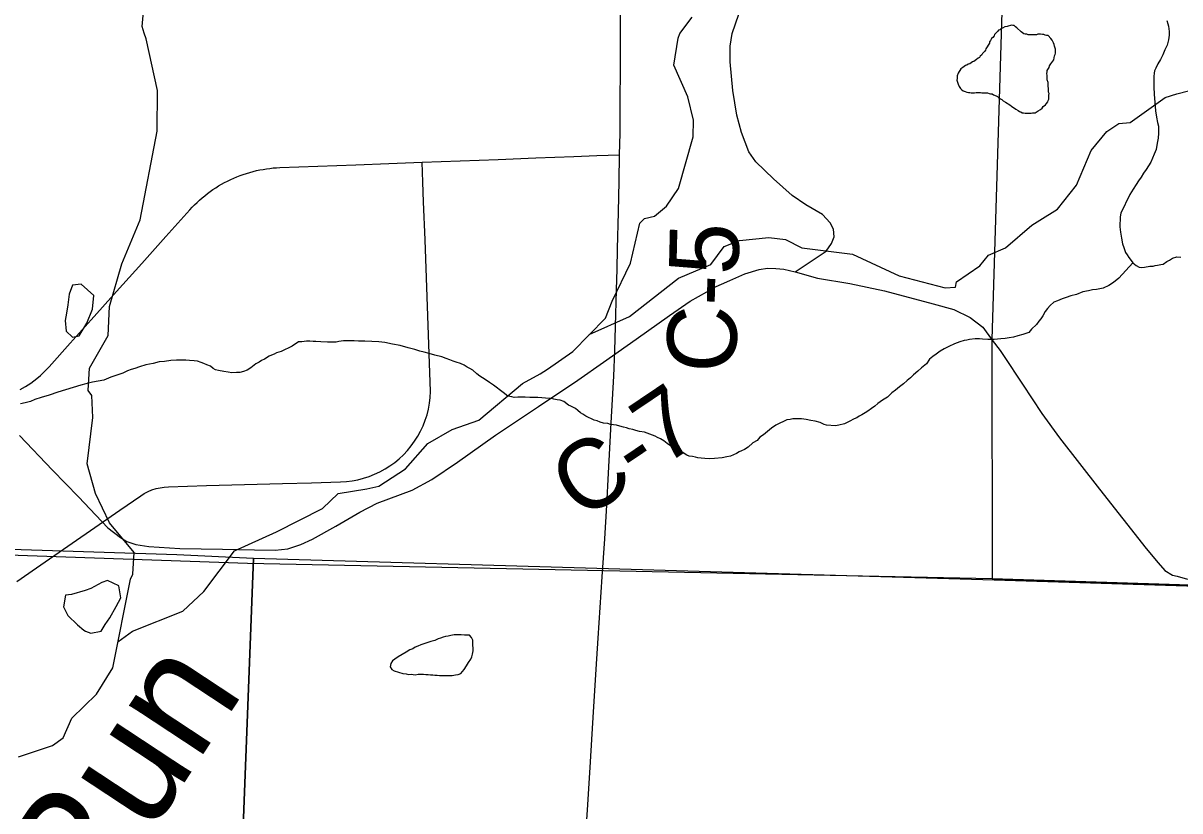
# Model space of a CAD drawing. Extents: x -6.1 to 38, y -7.7 to 22.
# Drawn here: x 7.096 to 8.043, y 14.701 to 15.345 of the extents above; entities that cross this region are included whole.
import ezdxf

# ---------------------------------------------------------------- set-up
doc = ezdxf.new("R2010")
doc.units = 0
for name, color, linetype in [('GM_X_Corporation', 7, 'Continuous'), ('GM_X_County_Road', 7, 'Continuous'), ('GM_X_County_Road_Text', 7, 'Continuous'), ('GM_X_Minor_Lake', 7, 'Continuous'), ('GM_X_Minor_River', 7, 'Continuous'), ('GM_X_Minor_River_Text', 7, 'Continuous'), ('GM_X_Township_Road', 7, 'Continuous')]:
    doc.layers.add(name, color=color, linetype=linetype)

msp = doc.modelspace()

# ---------------------------------------------------------------- linework, layer by layer
at = {"layer": 'GM_X_Corporation'}
msp.add_lwpolyline([(6.8881, 19.93659), (7.17492, 19.92346), (7.23616, 19.921), (8.02661, 19.88922), (8.02125, 19.70471), (8.02079, 19.68982), (8.0189, 19.62846), (7.99279, 18.77986), (7.97287, 17.92154), (7.97183, 17.87641), (7.95308, 17.06692), (7.95307, 17.06643), (7.93594, 16.3267), (7.92512, 16.10977), (7.91657, 15.91251), (7.90988, 15.74002), (7.90533, 15.62285), (7.88899, 15.0865), (7.88923, 14.89059), (7.27984, 14.90301), (6.7864, 14.92029)], dxfattribs=at)
for points in [[(8.9, 14.85918), (8.9, 19.87135), (8.53815, 19.88018), (8.02661, 19.88922), (8.02125, 19.70471), (8.02079, 19.68982), (8.0189, 19.62846), (7.99279, 18.77986), (7.97287, 17.92154), (7.97183, 17.87641), (7.95308, 17.06692), (7.95307, 17.06643), (7.93594, 16.3267), (7.92512, 16.10977), (7.91657, 15.91251), (7.90988, 15.74002), (7.90533, 15.62285), (7.88899, 15.0865), (7.88923, 14.89059), (8.1023, 14.88375), (8.27757, 14.87811), (8.6137, 14.86789)], [(3.19219, 14.1), (8.25437, 14.1), (8.26188, 14.35188), (8.27757, 14.87811), (8.1023, 14.88375), (7.88923, 14.89059), (7.27984, 14.90301), (6.7864, 14.92029), (6.27951, 14.93803), (5.74746, 14.95956), (5.18977, 14.97327), (5.0967, 14.97556), (4.28061, 14.99995), (4.24786, 15.00093), (3.22473, 15.03847), (3.22164, 14.89402), (3.20818, 14.53184), (3.19363, 14.14313)], [(6.25814, 14.1), (7.25364, 14.1), (7.28457, 14.90716), (7.22185, 14.91015), (6.83138, 14.92264), (6.46239, 14.93366), (6.28581, 14.93893)], [(7.25364, 14.1), (8.25716, 14.1), (8.27613, 14.8776), (7.89065, 14.88943), (7.58452, 14.89838), (7.28457, 14.90716)]]:
    msp.add_lwpolyline(points, close=True, dxfattribs=at)
at = {"layer": 'GM_X_County_Road'}
for points in [[(7.5572, 14.6891), (7.55845, 14.70992), (7.56033, 14.74093), (7.56141, 14.75898), (7.56251, 14.77702), (7.56454, 14.80802), (7.56565, 14.82501), (7.56676, 14.842), (7.5684, 14.86705), (7.57003, 14.89211), (7.57108, 14.90771), (7.57214, 14.92331), (7.57367, 14.95076), (7.57512, 14.97697), (7.57627, 14.99761), (7.57742, 15.01825), (7.57844, 15.0373), (7.57947, 15.05636), (7.5803, 15.07709), (7.58097, 15.09716), (7.58174, 15.12711), (7.58213, 15.14386), (7.58251, 15.16061), (7.58347, 15.19075), (7.58395, 15.216), (7.58424, 15.2376), (7.58462, 15.25536), (7.58481, 15.28512), (7.58493, 15.30399), (7.58505, 15.32285), (7.58482, 15.40613)], [(7.09099, 14.88831), (7.10718, 14.89956), (7.13273, 14.91724), (7.15827, 14.93492), (7.17531, 14.94671), (7.19235, 14.9585), (7.19529, 14.96035), (7.19837, 14.96196), (7.20154, 14.96331), (7.20486, 14.96438), (7.20823, 14.96518), (7.21164, 14.96572), (7.21509, 14.96596), (7.24615, 14.96684), (7.27721, 14.96772), (7.30826, 14.9686), (7.33207, 14.96927), (7.35587, 14.96994), (7.36065, 14.97022), (7.36543, 14.97081), (7.37013, 14.9717), (7.37477, 14.97288), (7.37932, 14.97436), (7.38377, 14.97613), (7.38808, 14.97816), (7.3923, 14.98046), (7.39633, 14.98302), (7.40022, 14.98584), (7.40392, 14.9889), (7.40742, 14.99218), (7.4107, 14.99568), (7.41373, 14.99937), (7.41652, 15.00326), (7.41908, 15.00731), (7.42136, 15.01151), (7.4234, 15.01586), (7.42516, 15.02031), (7.42663, 15.02487), (7.42777, 15.02951), (7.42867, 15.03423), (7.42924, 15.03897), (7.42953, 15.04376), (7.42839, 15.07481), (7.42725, 15.10586), (7.42612, 15.13691), (7.42499, 15.16796), (7.42385, 15.19901), (7.42326, 15.21527), (7.42266, 15.23154)], [(7.0938, 15.04557), (7.09816, 15.04808), (7.10238, 15.05083), (7.1074, 15.05463), (7.11029, 15.05705), (7.11394, 15.06049), (7.1174, 15.06414), (7.13461, 15.08332), (7.15182, 15.1025), (7.17257, 15.12563), (7.19332, 15.14876), (7.21298, 15.17067), (7.23265, 15.19259), (7.2345, 15.19463), (7.23644, 15.19663), (7.23843, 15.19858), (7.24051, 15.20047), (7.2426, 15.20231), (7.24473, 15.20408), (7.24691, 15.2058), (7.24915, 15.20746), (7.25147, 15.20907), (7.25379, 15.2106), (7.25611, 15.21208), (7.25853, 15.2135), (7.26095, 15.21485), (7.26346, 15.21613), (7.26597, 15.21735), (7.26848, 15.21849), (7.27104, 15.21957), (7.27365, 15.22059), (7.27625, 15.22154), (7.27891, 15.2224), (7.28156, 15.2232), (7.28426, 15.22394), (7.28696, 15.2246), (7.28971, 15.22518), (7.29246, 15.22568), (7.29521, 15.22612), (7.29795, 15.22649), (7.3007, 15.22678), (7.3035, 15.22699), (7.30629, 15.22715), (7.33734, 15.22832), (7.36838, 15.22949), (7.39552, 15.23052), (7.42266, 15.23154), (7.45371, 15.2327), (7.48475, 15.23387), (7.51579, 15.23503), (7.54684, 15.2362), (7.56554, 15.2369), (7.58424, 15.2376)], [(7.25934, 14.91485), (7.2854, 14.91434), (7.30232, 14.91414), (7.3126, 14.9152), (7.3234, 14.91866), (7.33298, 14.92297), (7.35203, 14.93365), (7.37177, 14.94503), (7.38594, 14.95246), (7.41451, 14.96315), (7.43054, 14.97174), (7.45167, 14.98614), (7.4828, 15.00821), (7.51787, 15.03167), (7.55016, 15.05304), (7.57105, 15.06784), (7.59777, 15.08672), (7.62495, 15.106), (7.64191, 15.11785), (7.65561, 15.12551), (7.66068, 15.12868), (7.67442, 15.1348), (7.68673, 15.14014), (7.69835, 15.14363), (7.70532, 15.14479), (7.71205, 15.14456), (7.71856, 15.14386), (7.72785, 15.14177)], [(7.72785, 15.14177), (7.7462, 15.13666), (7.77268, 15.13224), (7.80101, 15.1262), (7.84073, 15.11552), (7.85769, 15.11111), (7.87116, 15.10437), (7.88138, 15.09648), (7.8892, 15.08596), (7.89555, 15.07743), (7.89833, 15.07324)], [(7.89833, 15.07324), (7.9139, 15.04979), (7.92969, 15.02586), (7.9441, 15.00589), (7.97708, 14.96408), (8.01518, 14.91553), (8.02493, 14.90368), (8.03051, 14.89742), (8.03678, 14.8937), (8.04056, 14.8927)], [(7.09304, 15.00798), (7.12021, 14.9794), (7.14135, 14.95781), (7.15562, 14.94264), (7.16533, 14.93227), (7.17573, 14.92436), (7.18089, 14.92104), (7.18827, 14.91855), (7.19896, 14.91693), (7.22427, 14.91553), (7.25934, 14.91485)], [(8.04056, 14.8927), (8.04908, 14.89044)]]:
    msp.add_lwpolyline(points, dxfattribs=at)
at = {"layer": 'GM_X_Minor_Lake'}
for p, q in [((7.1328, 15.11492), (7.13168, 15.10801)), ((7.14062, 14.85303), (7.14579, 14.84869))]:
    msp.add_line(p, q, dxfattribs=at)
for points in [[(7.86124, 15.30449), (7.86049, 15.30221), (7.86049, 15.29993), (7.86012, 15.29879), (7.86126, 15.29537), (7.86203, 15.29347), (7.86317, 15.29195), (7.86432, 15.29082), (7.86546, 15.29006), (7.86698, 15.28931), (7.8685, 15.28893), (7.86964, 15.28856), (7.87078, 15.28856), (7.87192, 15.28818), (7.87458, 15.28819), (7.8761, 15.28858), (7.87952, 15.28859), (7.88066, 15.28821), (7.8818, 15.28822), (7.88522, 15.28823), (7.88674, 15.28785), (7.88788, 15.28748), (7.88902, 15.28748), (7.89016, 15.28672), (7.89244, 15.28597), (7.89358, 15.28522), (7.89472, 15.28408), (7.89587, 15.28332), (7.89701, 15.28295), (7.89815, 15.28181), (7.90005, 15.28068), (7.90348, 15.27841), (7.905, 15.27727), (7.90843, 15.27501), (7.91033, 15.27387), (7.91147, 15.27312), (7.91261, 15.27274), (7.91375, 15.27198), (7.91489, 15.27199), (7.91603, 15.27161), (7.91717, 15.27161), (7.91831, 15.27162), (7.92097, 15.27163), (7.92211, 15.27201), (7.92439, 15.27202), (7.92666, 15.27355), (7.92856, 15.27469), (7.93008, 15.27584), (7.93083, 15.27698), (7.93273, 15.27851), (7.93349, 15.27965), (7.93462, 15.2808), (7.935, 15.28194), (7.93538, 15.28308), (7.93537, 15.2865), (7.93575, 15.28764), (7.93536, 15.28878), (7.93535, 15.2922), (7.93497, 15.29334), (7.93496, 15.29676), (7.9342, 15.29904), (7.93419, 15.30018), (7.93418, 15.30246), (7.9338, 15.30398), (7.93418, 15.3055), (7.93418, 15.30664), (7.93569, 15.30893), (7.93606, 15.31045), (7.9372, 15.31197), (7.93947, 15.3154), (7.94022, 15.31844), (7.9406, 15.31959), (7.94098, 15.32073), (7.94097, 15.32415), (7.9402, 15.32643), (7.93982, 15.32795), (7.93943, 15.32908), (7.93867, 15.33022), (7.93829, 15.33136), (7.93715, 15.33288), (7.93486, 15.33515), (7.93372, 15.33515), (7.93258, 15.33552), (7.93144, 15.3359), (7.9303, 15.3359), (7.92878, 15.33627), (7.9265, 15.33626), (7.92536, 15.33588), (7.91852, 15.33585), (7.91738, 15.33623), (7.91624, 15.33623), (7.9151, 15.3366), (7.91282, 15.33812), (7.90939, 15.34153), (7.90825, 15.34228), (7.90711, 15.34342), (7.90597, 15.34341), (7.90483, 15.34379), (7.90141, 15.34264), (7.89951, 15.34225), (7.89752, 15.34133)], [(7.89752, 15.34133), (7.89686, 15.3411), (7.89534, 15.33996), (7.8942, 15.33957), (7.89344, 15.33843), (7.89117, 15.33614), (7.89079, 15.335), (7.88966, 15.33347), (7.88852, 15.33271), (7.88776, 15.33119), (7.88701, 15.33005), (7.88701, 15.3289), (7.88398, 15.32433), (7.88361, 15.32319), (7.88285, 15.32205), (7.88133, 15.32052), (7.88058, 15.31938), (7.87944, 15.31824), (7.87868, 15.31709), (7.87754, 15.31671), (7.87641, 15.31557), (7.87413, 15.31404), (7.87299, 15.31365), (7.87072, 15.31213), (7.86958, 15.31174), (7.86844, 15.31098), (7.8673, 15.31059), (7.86617, 15.30983), (7.86503, 15.30907), (7.86351, 15.30792), (7.86124, 15.30449)], [(7.13168, 15.10801), (7.13057, 15.10203), (7.13134, 15.09331), (7.13664, 15.08839), (7.14192, 15.08954), (7.14831, 15.09979), (7.15282, 15.11117), (7.15392, 15.12254), (7.1437, 15.13162), (7.13653, 15.13084), (7.13391, 15.12364), (7.1328, 15.11492)], [(7.14579, 14.84869), (7.14706, 14.84774), (7.15159, 14.84624), (7.15989, 14.84777), (7.16328, 14.85308), (7.16704, 14.85877), (7.1723, 14.86788), (7.17606, 14.87509), (7.17452, 14.88494), (7.16507, 14.88909), (7.16055, 14.88757), (7.1515, 14.88262), (7.14697, 14.8811), (7.13565, 14.87766), (7.13075, 14.87727), (7.12926, 14.86779), (7.13268, 14.8606), (7.14062, 14.85303)], [(7.45276, 14.84471), (7.4527, 14.84471), (7.4489, 14.84464), (7.44625, 14.84421), (7.44398, 14.84379), (7.44171, 14.84337), (7.43982, 14.84296), (7.43755, 14.84215), (7.43567, 14.84136), (7.43303, 14.84017), (7.42963, 14.83935), (7.42661, 14.83816), (7.42397, 14.83735), (7.4217, 14.83654), (7.41907, 14.83536), (7.4168, 14.83456), (7.41492, 14.83338), (7.41266, 14.83258), (7.40966, 14.83063), (7.40627, 14.82866), (7.40289, 14.8267), (7.40027, 14.82475), (7.39839, 14.82358), (7.39691, 14.82127), (7.39658, 14.8186), (7.39776, 14.81634), (7.39968, 14.81524), (7.40693, 14.81309), (7.4096, 14.81276), (7.4115, 14.81241), (7.41378, 14.81245), (7.41682, 14.81212), (7.41947, 14.81255), (7.42175, 14.81259), (7.42365, 14.81263), (7.42555, 14.81228), (7.42745, 14.81231), (7.42936, 14.81197), (7.43126, 14.812), (7.43316, 14.81166), (7.43506, 14.81169), (7.43696, 14.81134), (7.43962, 14.81139), (7.4438, 14.81147), (7.44721, 14.81153), (7.44986, 14.81196), (7.45214, 14.81238), (7.4544, 14.81318), (7.457, 14.81627), (7.45885, 14.81934), (7.4607, 14.82204), (7.46255, 14.82473), (7.46327, 14.82665), (7.46399, 14.82894), (7.46432, 14.83161), (7.46428, 14.83389), (7.46424, 14.83617), (7.4642, 14.83845), (7.46417, 14.84035), (7.46299, 14.84261), (7.46143, 14.84448)], [(7.46143, 14.84448), (7.45726, 14.84441), (7.4546, 14.84474), (7.45276, 14.84471)]]:
    msp.add_lwpolyline(points, dxfattribs=at)
at = {"layer": 'GM_X_Minor_River'}
for points in [[(7.09219, 14.74492), (7.12011, 14.75407), (7.12878, 14.76053), (7.13591, 14.77647), (7.15625, 14.79621), (7.1694, 14.81785), (7.18395, 14.89027), (7.18582, 14.89444), (7.18691, 14.91225), (7.16684, 14.93647), (7.15546, 14.96032), (7.1486, 14.98457), (7.15304, 15.02248), (7.15224, 15.04067), (7.14921, 15.04483), (7.15029, 15.06303), (7.16571, 15.08959), (7.16678, 15.11347), (7.17688, 15.14836), (7.1919, 15.1844), (7.20568, 15.25682), (7.20598, 15.29017), (7.19681, 15.3326), (7.19529, 15.33715), (7.19339, 15.34245), (7.1989, 15.40349)], [(7.17364, 14.83893), (7.18556, 14.84782), (7.22667, 14.8642), (7.244, 14.88016), (7.26921, 14.91356), (7.30353, 14.92917), (7.34123, 14.94819), (7.35404, 14.96034), (7.37743, 14.96418), (7.38724, 14.96647), (7.4091, 14.98054), (7.42717, 15.00142), (7.44715, 15.01282), (7.46902, 15.02045), (7.50481, 15.05045), (7.51914, 15.05844), (7.52517, 15.06224), (7.54589, 15.07668), (7.57263, 15.10402), (7.57825, 15.11767), (7.59328, 15.14878), (7.60075, 15.18177), (7.60451, 15.18556), (7.61281, 15.18747), (7.62261, 15.19545), (7.63239, 15.20987), (7.64436, 15.25234), (7.6447, 15.26598), (7.64012, 15.28493), (7.62873, 15.31106), (7.63208, 15.33305), (7.63358, 15.33684), (7.64374, 15.35012)], [(8.03197, 15.34751), (8.03278, 15.34486), (8.03357, 15.34297), (8.03361, 15.34069), (8.03403, 15.33842), (8.03409, 15.33538), (8.03339, 15.33156), (8.03233, 15.32736), (8.0305, 15.32353), (8.02868, 15.31931), (8.02684, 15.31548), (8.02463, 15.31201), (8.02317, 15.30857), (8.02207, 15.30627), (8.02173, 15.30436), (8.0214, 15.30169), (8.02146, 15.29827), (8.02155, 15.29295), (8.02165, 15.28725), (8.02216, 15.28041), (8.02266, 15.27358), (8.02351, 15.26827), (8.02435, 15.2641), (8.02516, 15.26107), (8.02521, 15.25841), (8.02526, 15.25537), (8.02496, 15.25118), (8.02427, 15.24699), (8.02322, 15.24203), (8.02177, 15.2382), (8.02031, 15.23475), (8.01885, 15.23168), (8.017, 15.22861), (8.01516, 15.22553), (8.01294, 15.22245), (8.01109, 15.21938), (8.00887, 15.21629), (8.00703, 15.21322), (8.00444, 15.20937), (8.00185, 15.20514), (7.99454, 15.1898), (7.99383, 15.18675), (7.99359, 15.17876), (7.99405, 15.1742), (7.9949, 15.16927), (7.99574, 15.16473), (7.99693, 15.16171), (7.99815, 15.15754), (7.9997, 15.15567), (8.00088, 15.15341), (8.00282, 15.15116), (8.00437, 15.14929), (8.00707, 15.14706), (8.00938, 15.14558), (8.01166, 15.14524), (8.01393, 15.14566), (8.0181, 15.1465), (8.02075, 15.14654), (8.02264, 15.14696), (8.02454, 15.14737), (8.02719, 15.1478), (8.02908, 15.14821), (8.03208, 15.15017), (8.03434, 15.15135), (8.03659, 15.15291), (8.04037, 15.15412), (8.04341, 15.15379)], [(7.55944, 15.09053), (7.59226, 15.10519), (7.63257, 15.13672), (7.65897, 15.14776), (7.66988, 15.16256), (7.68232, 15.16751), (7.70647, 15.16982), (7.72007, 15.16833), (7.73329, 15.16153), (7.77483, 15.1563), (7.813, 15.13855), (7.85077, 15.12876), (7.85908, 15.12915), (7.85982, 15.1337), (7.87904, 15.14662), (7.88619, 15.15535), (7.90014, 15.16143), (7.92161, 15.18004), (7.92802, 15.18422), (7.94272, 15.19296), (7.95814, 15.21269), (7.97015, 15.24114), (7.98294, 15.2567), (7.99274, 15.26316), (8.00218, 15.26393), (8.03081, 15.28444), (8.04024, 15.28749), (8.09984, 15.30275)], [(8.00437, 15.14929), (7.99283, 15.13654), (7.98833, 15.13303), (7.98458, 15.13069), (7.98006, 15.12832), (7.97438, 15.12746), (7.97135, 15.12703), (7.96795, 15.1262), (7.9634, 15.12536), (7.95812, 15.12337), (7.95359, 15.12215), (7.94981, 15.12094), (7.94642, 15.11973), (7.94265, 15.11815), (7.93963, 15.11695), (7.93664, 15.11424), (7.9344, 15.11191), (7.93255, 15.10922), (7.93072, 15.10576), (7.92886, 15.10345), (7.92737, 15.10152), (7.92552, 15.09883), (7.92141, 15.09495), (7.91918, 15.09225), (7.91427, 15.09064), (7.91012, 15.08943), (7.90672, 15.08822), (7.90293, 15.08778), (7.8999, 15.08734), (7.89611, 15.08689), (7.8908, 15.08642), (7.88549, 15.08632), (7.88131, 15.08663), (7.87864, 15.08696), (7.87522, 15.0869), (7.87068, 15.08644), (7.8684, 15.08601), (7.86613, 15.08559), (7.86274, 15.08439), (7.85821, 15.08279), (7.85369, 15.08081), (7.84992, 15.07884), (7.84654, 15.07688), (7.84317, 15.07454), (7.84054, 15.07259), (7.83793, 15.07026), (7.83533, 15.06641), (7.83121, 15.06329), (7.82822, 15.06058), (7.82486, 15.05748), (7.82224, 15.05515), (7.81963, 15.05282), (7.81664, 15.05011), (7.81326, 15.04776), (7.80989, 15.04504), (7.8069, 15.04271), (7.80354, 15.03922), (7.7994, 15.03687), (7.79566, 15.03414), (7.79304, 15.03181), (7.79042, 15.02986), (7.78741, 15.02791), (7.78516, 15.02635), (7.78253, 15.02478), (7.78027, 15.0236), (7.7784, 15.02242), (7.77613, 15.02162), (7.772, 15.01927), (7.76823, 15.0173), (7.76369, 15.01646), (7.76105, 15.01565), (7.75344, 15.01627), (7.75153, 15.017), (7.74847, 15.01846), (7.74427, 15.01953), (7.74084, 15.02023), (7.73703, 15.02092), (7.73322, 15.02161), (7.72866, 15.02153), (7.726, 15.02148), (7.72373, 15.02106), (7.72108, 15.02063), (7.71844, 15.01945), (7.71543, 15.01787), (7.71204, 15.01629), (7.70867, 15.01395), (7.7053, 15.01122), (7.70193, 15.0085), (7.69893, 15.00655), (7.6967, 15.00385), (7.69331, 15.00188), (7.68958, 14.99839), (7.68657, 14.99644), (7.68394, 14.99525), (7.68205, 14.99446), (7.6798, 14.99328), (7.67754, 14.99209), (7.6749, 14.99091), (7.67187, 14.99047), (7.66809, 14.98964), (7.66202, 14.98915)], [(7.33333, 15.08477), (7.33067, 15.0851), (7.32801, 15.08505), (7.32422, 15.08461), (7.32157, 15.08456), (7.31631, 15.08104), (7.30727, 15.0767), (7.3035, 15.07549), (7.30162, 15.07431), (7.29936, 15.07351), (7.29747, 15.07272), (7.29372, 15.07037), (7.29108, 15.06918), (7.2892, 15.06801), (7.28657, 15.06644), (7.28245, 15.06332), (7.27945, 15.06137), (7.27643, 15.06017), (7.27341, 15.05936), (7.27075, 15.05931), (7.26695, 15.05924), (7.26391, 15.05957), (7.26048, 15.06027), (7.25591, 15.06094), (7.25362, 15.06166), (7.2517, 15.06277), (7.24939, 15.06463), (7.24633, 15.06572), (7.24403, 15.06681), (7.24174, 15.06753), (7.23868, 15.06862), (7.23602, 15.06895), (7.23222, 15.06926), (7.22917, 15.06959), (7.22575, 15.06953), (7.22158, 15.06945), (7.21702, 15.06937), (7.21172, 15.06851), (7.20755, 15.06806), (7.20264, 15.06683), (7.19658, 15.06558), (7.1913, 15.06397), (7.18752, 15.06276), (7.1845, 15.06194), (7.18148, 15.06075), (7.17772, 15.05878), (7.17281, 15.05717), (7.1679, 15.05556), (7.16225, 15.05318), (7.15278, 15.05148), (7.14749, 15.05025), (7.14333, 15.04903), (7.12445, 15.04337), (7.11728, 15.04096), (7.11086, 15.03894), (7.10557, 15.03733), (7.10218, 15.03575), (7.09764, 15.03452), (7.09386, 15.03369)], [(7.66202, 14.98915), (7.65747, 14.98869), (7.65405, 14.98901), (7.651, 14.98934), (7.64834, 14.98967), (7.64643, 14.99002), (7.64376, 14.99073), (7.6411, 14.99106), (7.63919, 14.99179), (7.63612, 14.99363), (7.63343, 14.99549), (7.62999, 14.99656), (7.62769, 14.99766), (7.62576, 14.99953), (7.62307, 15.00138), (7.62037, 15.00362), (7.61768, 15.00509), (7.61538, 15.00619), (7.61347, 15.00729), (7.60467, 15.01056), (7.60048, 15.01124), (7.59743, 15.01195), (7.59514, 15.01267), (7.59209, 15.01337), (7.5898, 15.01409), (7.58751, 15.01481), (7.58446, 15.01552), (7.58179, 15.01623), (7.57912, 15.01656), (7.57684, 15.0169), (7.57454, 15.01762), (7.57112, 15.01794), (7.56845, 15.01865), (7.56577, 15.01975), (7.56348, 15.02047), (7.56118, 15.02156), (7.55888, 15.02266), (7.55658, 15.02376), (7.55428, 15.02524), (7.55236, 15.02635), (7.55005, 15.02821), (7.54812, 15.03008), (7.54429, 15.03191), (7.54238, 15.03263), (7.53852, 15.03561), (7.53547, 15.03669), (7.53318, 15.03703), (7.53051, 15.03774), (7.52861, 15.03809), (7.52671, 15.03806), (7.52366, 15.03838), (7.52062, 15.03871), (7.5172, 15.03902), (7.51416, 15.03897), (7.51074, 15.03891), (7.50694, 15.03922), (7.50352, 15.03916), (7.50086, 15.03911), (7.49783, 15.03906), (7.49592, 15.0394), (7.49287, 15.04011), (7.48902, 15.04308), (7.48094, 15.04902), (7.47786, 15.05125), (7.47517, 15.0531), (7.4721, 15.05495), (7.46979, 15.05643), (7.46748, 15.05829), (7.46401, 15.06126), (7.46171, 15.06274), (7.45941, 15.06384), (7.4571, 15.06532), (7.45404, 15.06679), (7.4506, 15.06787), (7.44793, 15.06858), (7.44525, 15.06967), (7.4422, 15.07076), (7.43875, 15.07222), (7.43303, 15.07363), (7.42845, 15.07507), (7.42425, 15.07614), (7.42082, 15.07684), (7.41662, 15.07828), (7.41127, 15.07971), (7.40479, 15.08149), (7.39831, 15.08252), (7.39221, 15.08393), (7.38726, 15.0846), (7.38156, 15.08488), (7.37586, 15.08515), (7.37054, 15.08506), (7.36712, 15.08538), (7.36257, 15.0853), (7.35839, 15.08522), (7.3546, 15.08477), (7.35233, 15.08435), (7.34929, 15.0843), (7.34511, 15.08422), (7.33979, 15.08451), (7.33561, 15.08481), (7.33333, 15.08477)]]:
    msp.add_lwpolyline(points, dxfattribs=at)
at = {"layer": 'GM_X_Township_Road'}
msp.add_lwpolyline([(7.72785, 15.14177), (7.73783, 15.14827), (7.75316, 15.15873), (7.75758, 15.165), (7.75991, 15.17034), (7.7592, 15.17661), (7.75665, 15.18195), (7.75015, 15.18869), (7.73667, 15.19659), (7.72552, 15.20425), (7.7102, 15.21796), (7.69579, 15.23189), (7.68998, 15.24004), (7.68391, 15.25577), (7.68009, 15.26993), (7.67694, 15.29016), (7.67469, 15.31376), (7.67469, 15.32657), (7.67649, 15.33691), (7.68189, 15.35264)], dxfattribs=at)

# ---------------------------------------------------------------- texts
at = {"layer": 'GM_X_County_Road_Text'}
for s, rotation, p in [('C-5', 88.62666, (7.67938, 15.05875)), ('C-7', 33.95328, (7.55325, 14.93719))]:
    msp.add_text(s, height=0.056818, rotation=rotation, dxfattribs=at).set_placement(p)
at = {"layer": 'GM_X_Minor_River_Text'}
msp.add_text('Run', height=0.094679, rotation=56.5989, dxfattribs=at).set_placement((7.14955, 14.60465))

doc.saveas('drawing.dxf')
